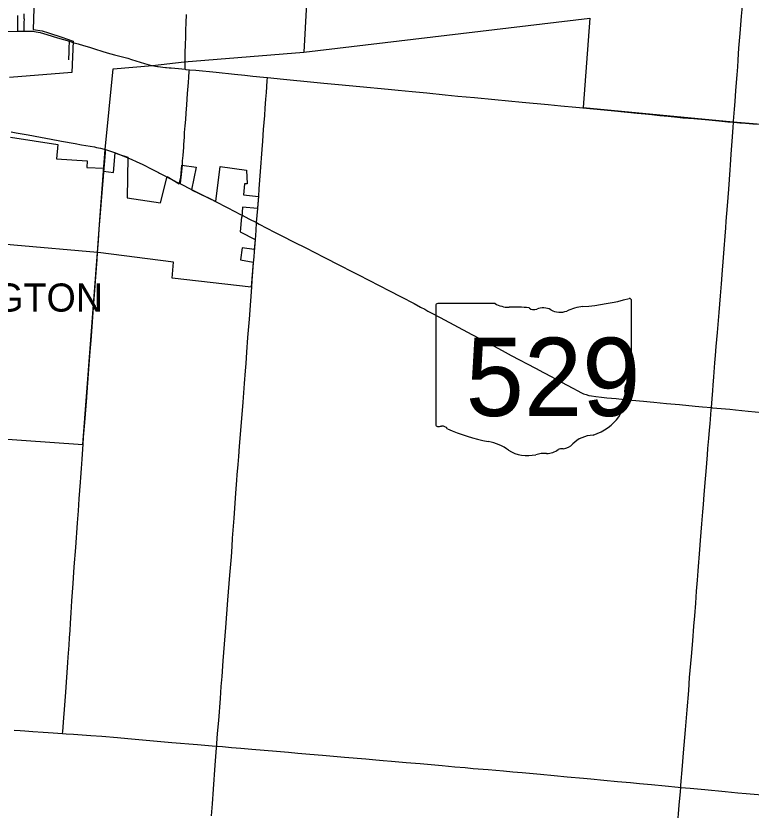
# Model space of a CAD drawing. Extents: x 9078 to 9739, y 4248 to 4966.
# Drawn here: x 9309.1 to 9374.4, y 4486.1 to 4556.7 of the extents above; entities that cross this region are included whole.
import ezdxf

# ---------------------------------------------------------------- set-up
doc = ezdxf.new("R2010")
doc.units = 0
for name, color, linetype in [('GM_X_City_Street', 7, 'Continuous'), ('GM_X_Corporation', 7, 'Continuous'), ('GM_X_Corporation_Text', 7, 'Continuous'), ('GM_X_County_Road', 7, 'Continuous'), ('GM_X_State_Route', 7, 'Continuous'), ('GM_X_State_Shield', 7, 'Continuous'), ('GM_X_Township', 7, 'Continuous'), ('GM_X_Township_Road', 7, 'Continuous')]:
    doc.layers.add(name, color=color, linetype=linetype)

msp = doc.modelspace()

# ---------------------------------------------------------------- linework, layer by layer
at = {"layer": 'GM_X_City_Street'}
for points in [[(9309.22, 4556.731), (9309.235, 4555.67), (9309.233, 4555.507), (9309.231, 4555.326)], [(9309.824, 4555.33), (9309.824, 4555.467), (9309.826, 4556.126), (9309.831, 4556.376), (9309.828, 4556.457), (9309.828, 4556.623), (9309.821, 4556.87)], [(9302.627, 4555.284), (9303.028, 4555.281), (9303.757, 4555.282), (9304.823, 4555.283), (9306.792, 4555.305), (9309.231, 4555.326)], [(9309.231, 4555.326), (9309.824, 4555.33)], [(9309.824, 4555.33), (9310.32, 4555.335), (9310.602, 4555.329)], [(9313.792, 4552.795), (9313.812, 4553.523), (9313.821, 4554.008), (9313.835, 4554.251), (9313.847, 4554.435)], [(9316.344, 4535.633), (9316.418, 4536.731), (9316.494, 4537.724), (9316.867, 4542.425)]]:
    msp.add_lwpolyline(points, dxfattribs=at)
at = {"layer": 'GM_X_Corporation'}
for points in [[(9310.88, 4563.986), (9310.619, 4555.475), (9311.421, 4555.361), (9311.99, 4555.188), (9313.163, 4554.81), (9314.157, 4554.446), (9314.059, 4551.658), (9308.511, 4551.22)], [(9308.601, 4545.914), (9312.796, 4545.263), (9312.703, 4543.979), (9315.425, 4543.825), (9315.391, 4543.233), (9316.896, 4543.157), (9316.875, 4542.9), (9317.752, 4542.778), (9317.893, 4544.527), (9318.116, 4544.443), (9319.016, 4544.146), (9318.961, 4540.535), (9321.926, 4540.083), (9322.519, 4542.409), (9323.607, 4541.777), (9323.743, 4542.36), (9323.817, 4543.417), (9325.109, 4543.241), (9324.69, 4541.244), (9326.857, 4540.203), (9327.242, 4543.297), (9329.581, 4542.977), (9329.635, 4541.757), (9329.401, 4541.78), (9329.321, 4540.784), (9330.633, 4540.653), (9330.547, 4539.562), (9329.232, 4539.687), (9329.162, 4538.81), (9329.131, 4538.826), (9329.024, 4537.501), (9330.341, 4536.813), (9330.264, 4535.928), (9329.181, 4536.066), (9329.032, 4534.999), (9330.181, 4534.801), (9330.007, 4532.582), (9322.984, 4533.397), (9323.098, 4534.807), (9316.388, 4535.671), (9316.326, 4535.676), (9294.005, 4537.618)]]:
    msp.add_lwpolyline(points, dxfattribs=at)
at = {"layer": 'GM_X_County_Road'}
for points in [[(9372.874, 4547.239), (9372.88, 4547.353), (9372.96, 4548.417), (9373.008, 4549.072), (9373.088, 4550.053), (9373.19, 4551.443), (9373.243, 4552.177), (9373.286, 4552.748), (9373.324, 4553.321), (9373.36, 4553.812), (9373.469, 4555.12), (9373.597, 4556.674), (9373.678, 4557.572)], [(9370.91, 4521.874), (9370.978, 4522.656), (9371.038, 4523.392), (9371.077, 4523.882), (9371.132, 4524.618), (9371.225, 4525.844), (9371.277, 4526.498), (9371.341, 4527.316), (9371.441, 4528.542), (9371.584, 4530.341), (9371.71, 4531.812), (9371.793, 4532.876), (9371.887, 4534.102), (9371.943, 4534.839), (9372.044, 4535.983), (9372.132, 4537.128), (9372.186, 4537.864), (9372.232, 4538.437), (9372.339, 4539.826), (9372.396, 4540.563), (9372.454, 4541.298), (9372.575, 4543.017), (9372.603, 4543.426), (9372.674, 4544.408), (9372.758, 4545.553), (9372.847, 4546.78), (9372.874, 4547.239)], [(9316.928, 4543.154), (9316.983, 4543.805), (9317.039, 4544.551), (9317.044, 4544.634), (9317.054, 4544.816)], [(9316.867, 4542.425), (9316.928, 4543.154)], [(9330.367, 4536.799), (9330.428, 4537.615), (9330.478, 4538.321)], [(9330.281, 4535.742), (9330.367, 4536.799)], [(9330.206, 4534.739), (9330.25, 4535.269), (9330.281, 4535.742)], [(9315.38, 4522.817), (9315.447, 4523.667), (9315.473, 4524.076), (9315.531, 4524.893), (9315.592, 4525.711), (9315.682, 4526.856), (9315.756, 4527.837), (9315.845, 4529.064), (9315.949, 4530.372), (9316.061, 4531.926), (9316.212, 4533.888), (9316.303, 4535.032), (9316.344, 4535.633)], [(9330.041, 4532.598), (9330.084, 4533.189), (9330.206, 4534.739)], [(9326.933, 4491.784), (9326.944, 4492.024), (9327.014, 4492.908), (9327.106, 4494.054), (9327.253, 4496.019), (9327.339, 4497.082), (9327.408, 4497.983), (9327.517, 4499.374), (9327.737, 4502.322), (9327.93, 4504.777), (9328.112, 4506.986), (9328.236, 4508.624), (9328.295, 4509.524), (9328.349, 4510.261), (9328.478, 4512.063), (9328.636, 4514.274), (9328.727, 4515.42), (9328.76, 4515.911), (9328.828, 4516.811), (9328.888, 4517.547), (9328.961, 4518.447), (9329.069, 4519.839), (9329.277, 4522.375), (9329.405, 4524.012), (9329.487, 4525.158), (9329.54, 4525.812), (9329.605, 4526.796), (9329.707, 4528.105), (9329.835, 4529.742), (9329.952, 4531.38), (9330.041, 4532.598)], [(9315.06, 4518.632), (9315.102, 4519.252), (9315.208, 4520.56), (9315.376, 4522.768), (9315.38, 4522.817)], [(9368.184, 4488.123), (9368.199, 4488.321), (9368.331, 4490.039), (9368.432, 4491.183), (9368.607, 4493.226), (9368.751, 4495.025), (9368.888, 4496.742), (9368.973, 4497.887), (9369.124, 4499.768), (9369.245, 4501.157), (9369.348, 4502.466), (9369.425, 4503.365), (9369.515, 4504.509), (9369.588, 4505.573), (9369.662, 4506.555), (9369.724, 4507.373), (9369.876, 4509.253), (9369.939, 4510.071), (9370.063, 4511.542), (9370.142, 4512.606), (9370.194, 4513.26), (9370.263, 4514.159), (9370.391, 4515.546), (9370.447, 4516.2), (9370.504, 4516.936), (9370.564, 4517.672), (9370.602, 4518.244), (9370.674, 4519.142), (9370.735, 4519.878), (9370.785, 4520.45), (9370.892, 4521.676), (9370.91, 4521.874)], [(9313.693, 4499.228), (9313.727, 4499.705), (9313.806, 4500.768), (9313.85, 4501.422), (9313.894, 4502.077), (9313.937, 4502.731), (9313.991, 4503.631), (9314.061, 4504.695), (9314.169, 4506.249), (9314.202, 4506.74), (9314.268, 4507.721), (9314.396, 4509.438), (9314.562, 4511.646), (9314.635, 4512.71), (9314.71, 4513.773), (9314.819, 4515.245), (9314.846, 4515.654), (9314.901, 4516.471), (9314.961, 4517.289), (9315.031, 4518.189), (9315.06, 4518.632)], [(9313.223, 4492.911), (9313.237, 4493.082), (9313.341, 4494.307), (9313.393, 4495.043), (9313.505, 4496.597), (9313.693, 4499.228)], [(9308.935, 4493.209), (9309.452, 4493.176), (9309.861, 4493.149), (9310.598, 4493.095), (9311.497, 4493.033), (9312.397, 4492.968), (9313.223, 4492.911)], [(9313.223, 4492.911), (9313.542, 4492.889), (9314.197, 4492.843), (9315.75, 4492.729), (9316.733, 4492.661), (9318.122, 4492.545), (9319.021, 4492.47), (9320.655, 4492.326), (9322.942, 4492.125), (9325.231, 4491.931), (9326.537, 4491.814), (9326.933, 4491.784)], [(9326.47, 4485.601), (9326.546, 4486.664), (9326.646, 4487.972), (9326.806, 4490.097), (9326.923, 4491.65), (9326.933, 4491.784)], [(9326.933, 4491.784), (9327.437, 4491.746), (9328.254, 4491.676), (9329.071, 4491.605), (9330.052, 4491.52), (9332.258, 4491.33), (9333.32, 4491.238), (9334.137, 4491.171), (9335.2, 4491.081), (9336.343, 4490.978), (9338.305, 4490.822), (9340.184, 4490.657), (9341.083, 4490.583), (9341.736, 4490.524), (9342.471, 4490.458), (9343.779, 4490.348), (9345.004, 4490.239), (9346.965, 4490.064), (9348.108, 4489.962), (9349.007, 4489.881), (9349.742, 4489.814), (9351.05, 4489.707), (9352.438, 4489.584), (9353.255, 4489.508), (9354.072, 4489.432), (9355.706, 4489.287), (9356.931, 4489.177), (9358.074, 4489.072), (9359.544, 4488.936), (9360.197, 4488.87), (9361.34, 4488.771), (9362.565, 4488.659), (9363.708, 4488.55), (9364.524, 4488.467), (9365.585, 4488.368), (9366.81, 4488.252), (9367.953, 4488.145), (9368.184, 4488.123)], [(9363.15, 4461.203), (9364.003, 4463.694), (9364.89, 4466.251), (9365.379, 4467.644), (9366.623, 4471.206), (9366.786, 4471.754), (9366.839, 4471.964), (9366.858, 4472.051), (9366.871, 4472.126), (9366.891, 4472.255), (9366.902, 4472.346), (9366.917, 4472.5), (9366.947, 4472.886), (9367.15, 4475.502), (9367.38, 4478.281), (9367.537, 4480.243), (9367.643, 4481.551), (9367.774, 4483.103), (9367.9, 4484.656), (9368.043, 4486.537), (9368.147, 4487.769), (9368.184, 4488.123)], [(9368.184, 4488.123), (9369.014, 4488.046), (9370.32, 4487.925), (9372.116, 4487.756), (9373.259, 4487.646), (9373.993, 4487.575), (9375.054, 4487.485), (9375.216, 4487.47)]]:
    msp.add_lwpolyline(points, dxfattribs=at)
at = {"layer": 'GM_X_State_Route'}
for points in [[(9308.654, 4546.389), (9309.097, 4546.311), (9310.156, 4546.122), (9312.846, 4545.62)], [(9312.846, 4545.62), (9313.143, 4545.567), (9314.355, 4545.349), (9314.911, 4545.249), (9316.052, 4545.045), (9316.259, 4545.003)], [(9316.259, 4545.003), (9316.614, 4544.93), (9316.932, 4544.852), (9317.054, 4544.816), (9317.324, 4544.736), (9317.926, 4544.525)], [(9317.926, 4544.525), (9318.081, 4544.468), (9319.035, 4544.085)], [(9319.035, 4544.085), (9319.392, 4543.934), (9319.764, 4543.764), (9320.352, 4543.477), (9321.153, 4543.066), (9321.742, 4542.769)], [(9321.742, 4542.769), (9321.844, 4542.716), (9322.992, 4542.134), (9323.562, 4541.836), (9323.697, 4541.768)], [(9323.697, 4541.768), (9324.689, 4541.271)], [(9324.689, 4541.271), (9325.574, 4540.819), (9326.426, 4540.395)], [(9326.426, 4540.395), (9326.77, 4540.214), (9327.928, 4539.625), (9329.057, 4539.045), (9329.197, 4538.969)], [(9329.197, 4538.969), (9329.784, 4538.671), (9330.478, 4538.321), (9330.7, 4538.197), (9332.067, 4537.485), (9332.728, 4537.154), (9333.822, 4536.594), (9334.851, 4536.083), (9336.455, 4535.254), (9337.914, 4534.502), (9338.934, 4533.975), (9339.594, 4533.643), (9340.397, 4533.232), (9341.422, 4532.711), (9342.223, 4532.295), (9343.316, 4531.73), (9344.481, 4531.125), (9345.058, 4530.813), (9345.42, 4530.62), (9345.709, 4530.464), (9346.067, 4530.266), (9346.79, 4529.877), (9349.619, 4528.382), (9351.138, 4527.568), (9352.297, 4526.952), (9353.092, 4526.523), (9355.268, 4525.378), (9355.994, 4524.995), (9356.717, 4524.607), (9357.149, 4524.375), (9358.087, 4523.878), (9358.59, 4523.601), (9359.02, 4523.363), (9359.311, 4523.213), (9359.535, 4523.116), (9359.764, 4523.032), (9359.999, 4522.964), (9360.238, 4522.913), (9360.643, 4522.856), (9361.131, 4522.803), (9361.621, 4522.76), (9362.436, 4522.687), (9363.168, 4522.61), (9363.822, 4522.551), (9364.883, 4522.455), (9365.453, 4522.389), (9365.778, 4522.354), (9366.35, 4522.309), (9366.922, 4522.257), (9368.065, 4522.15), (9369.453, 4522.014), (9370.103, 4521.953), (9370.91, 4521.874), (9371, 4521.866), (9372.551, 4521.725), (9373.04, 4521.675), (9374.182, 4521.572), (9375.406, 4521.458)]]:
    msp.add_lwpolyline(points, dxfattribs=at)
at = {"layer": 'GM_X_State_Shield'}
for p, q in [((9346.406, 4530.954), (9346.406, 4520.388)), ((9351.673, 4531.136), (9346.577, 4531.136)), ((9363.808, 4525.87), (9363.808, 4531.398)), ((9363.806, 4525.872), (9363.808, 4525.87))]:
    msp.add_line(p, q, dxfattribs=at)
for centre, major_axis, start_param, end_param in [((9357.609, 4545.541), (18.455, 0), 4.814394, 5.042369), ((9363.615, 4531.421), (0.194, 0), 6.141152, 7.989035), ((9346.605, 4530.977), (0.202, 0), 1.712693, 3.28349), ((9352.887, 4532.363), (1.955, 0), 4.042523, 4.731795), ((9353.535, 4525.204), (7.02, 0), 1.404758, 1.657858), ((9355.957, 4529.81), (1.173, 0), 0.950623, 2.079405), ((9359.963, 4527.909), (3.713, 0), 1.699011, 2.107814), ((9355.129, 4531.031), (0.564, 0), 3.836095, 5.185415), ((9357.471, 4531.485), (1.411, 0), 4.081561, 5.145723), ((9363.601, 4525.849), (0.207, 0), 5.05454, 6.418171), ((9363.763, 4525.465), (0.3, 0), 1.883978, 3.671073), ((9361.856, 4524.766), (1.8, 0), 5.934695, 6.695948), ((9364.502, 4523.557), (1.309, 0), 2.387724, 3.262537), ((9358.643, 4522.854), (4.616, 0), 5.101752, 6.440018), ((9346.607, 4520.365), (0.203, 0), 3.00124, 4.508301), ((9346.638, 4521.446), (1.552, 0), 4.665946, 4.897461), ((9346.955, 4519.778), (0.56, 0), 0.519207, 1.627899), ((9354.021, 4529.272), (13.327, 0), 4.195997, 4.488961), ((9350.048, 4515.641), (4.17, 0), 0.823519, 1.323587), ((9360.589, 4517.421), (2.528, 0), 1.647645, 2.488434), ((9354.558, 4519.726), (2.646, 0), 4.026481, 4.996735), ((9356.28, 4518.934), (1.41, 0), 4.691044, 5.507374), ((9357.555, 4517.911), (0.397, 0), 1.147584, 2.315152), ((9357.386, 4519.364), (1.491, 0), 4.937069, 5.64225), ((9356.087, 4516.073), (2.174, 0), 1.495662, 1.94098)]:
    msp.add_ellipse(centre, major_axis=major_axis, ratio=0.8, start_param=start_param, end_param=end_param, dxfattribs=at)
at = {"layer": 'GM_X_Township'}
for points in [[(9312.647, 4658.232), (9312.261, 4631.593), (9319.031, 4631.42), (9322.506, 4631.285), (9323.21, 4631.298), (9334.307, 4630.93), (9337.049, 4630.853), (9337.941, 4630.782), (9337.951, 4630.023), (9337.165, 4610.668), (9336.171, 4584.222), (9335.616, 4570.813), (9334.675, 4553.48)], [(9268.699, 4425.694), (9269.561, 4439.455), (9271.281, 4466.878), (9273.006, 4495.59), (9279.838, 4495.183), (9281.137, 4512.561), (9281.77, 4520.946), (9292.78, 4520.165), (9315.037, 4518.585), (9316.326, 4535.676), (9316.532, 4538.568), (9316.875, 4542.9), (9317.028, 4544.828), (9317.718, 4551.986), (9321.229, 4552.295), (9324.029, 4552.602), (9334.675, 4553.48), (9360.11, 4556.507), (9359.515, 4548.555), (9366.319, 4547.914), (9372.855, 4547.273), (9397.659, 4545.2), (9410.412, 4544.235)]]:
    msp.add_lwpolyline(points, dxfattribs=at)
at = {"layer": 'GM_X_Township_Road'}
for points in [[(9324.123, 4552.254), (9324.12, 4552.722), (9324.127, 4553.05), (9324.138, 4553.542), (9324.156, 4554.035), (9324.18, 4554.937), (9324.194, 4555.43), (9324.214, 4556.086), (9324.242, 4556.825)], [(9310.602, 4555.329), (9310.729, 4555.315), (9310.894, 4555.286), (9311.23, 4555.213), (9311.839, 4555.038), (9312.787, 4554.752), (9313.847, 4554.435)], [(9313.847, 4554.435), (9313.99, 4554.392), (9314.148, 4554.342)], [(9314.148, 4554.342), (9314.625, 4554.207), (9315.096, 4554.068), (9315.618, 4553.91)], [(9315.618, 4553.91), (9315.722, 4553.879), (9316.154, 4553.74), (9316.731, 4553.556), (9317.207, 4553.42), (9317.836, 4553.234), (9318.554, 4553.049), (9319.032, 4552.926), (9319.348, 4552.831), (9320.126, 4552.57), (9320.52, 4552.451), (9320.916, 4552.343), (9321.156, 4552.29), (9321.479, 4552.234), (9321.666, 4552.206)], [(9321.666, 4552.206), (9321.722, 4552.198), (9322.131, 4552.149), (9322.376, 4552.122), (9322.457, 4552.113), (9322.716, 4552.088)], [(9322.716, 4552.088), (9322.882, 4552.072), (9323.535, 4552.006), (9324.121, 4551.95)], [(9324.121, 4551.95), (9324.123, 4552.254)], [(9324.121, 4551.95), (9324.188, 4551.945), (9324.498, 4551.915)], [(9323.875, 4543.423), (9323.899, 4543.798), (9323.94, 4544.29), (9323.996, 4545.025), (9324.012, 4545.271), (9324.054, 4545.925), (9324.08, 4546.336), (9324.128, 4546.911), (9324.178, 4547.485), (9324.222, 4548.06), (9324.278, 4548.799), (9324.314, 4549.291), (9324.348, 4549.784), (9324.408, 4550.77), (9324.443, 4551.262), (9324.484, 4551.755), (9324.498, 4551.915)], [(9324.498, 4551.915), (9325.088, 4551.859), (9326.886, 4551.679), (9328.521, 4551.523), (9329.419, 4551.428), (9330.154, 4551.347), (9331.096, 4551.256), (9331.441, 4551.222)], [(9330.669, 4540.664), (9330.718, 4541.309), (9330.826, 4542.86), (9330.974, 4544.818), (9331.029, 4545.553), (9331.096, 4546.609), (9331.198, 4547.837), (9331.242, 4548.488), (9331.306, 4549.308), (9331.342, 4549.879), (9331.414, 4550.911), (9331.441, 4551.222)], [(9331.441, 4551.222), (9332.862, 4551.078), (9335.556, 4550.812), (9336.454, 4550.725), (9337.761, 4550.595), (9339.639, 4550.411), (9342.172, 4550.18), (9343.07, 4550.092), (9344.296, 4549.978), (9345.603, 4549.853), (9347.235, 4549.686), (9348.378, 4549.572), (9349.848, 4549.43), (9351.644, 4549.253), (9354.095, 4549.029), (9356.383, 4548.818), (9357.526, 4548.708), (9358.849, 4548.59)], [(9358.849, 4548.59), (9362.006, 4548.275), (9364.293, 4548.052), (9365.029, 4547.981), (9365.6, 4547.924), (9366.335, 4547.852), (9367.07, 4547.776), (9367.886, 4547.692), (9368.376, 4547.647), (9369.357, 4547.562), (9370.665, 4547.442), (9371.563, 4547.36), (9372.381, 4547.283), (9372.874, 4547.239)], [(9372.874, 4547.239), (9373.441, 4547.189), (9373.932, 4547.157), (9374.913, 4547.068)], [(9323.697, 4541.768), (9323.701, 4541.794), (9323.745, 4542.086), (9323.774, 4542.326), (9323.875, 4543.423)], [(9330.581, 4539.566), (9330.586, 4539.635), (9330.669, 4540.664)], [(9330.478, 4538.321), (9330.581, 4539.566)]]:
    msp.add_lwpolyline(points, dxfattribs=at)

# ---------------------------------------------------------------- texts
at = {"layer": 'GM_X_Corporation_Text'}
msp.add_text('CARDINGTON', height=2.5, rotation=0.00001, dxfattribs=at).set_placement((9294.344, 4530.41))
at = {"layer": 'GM_X_State_Shield'}
msp.add_text('529', height=6.961, dxfattribs=at).set_placement((9349.063, 4521.133))

doc.saveas('drawing.dxf')
